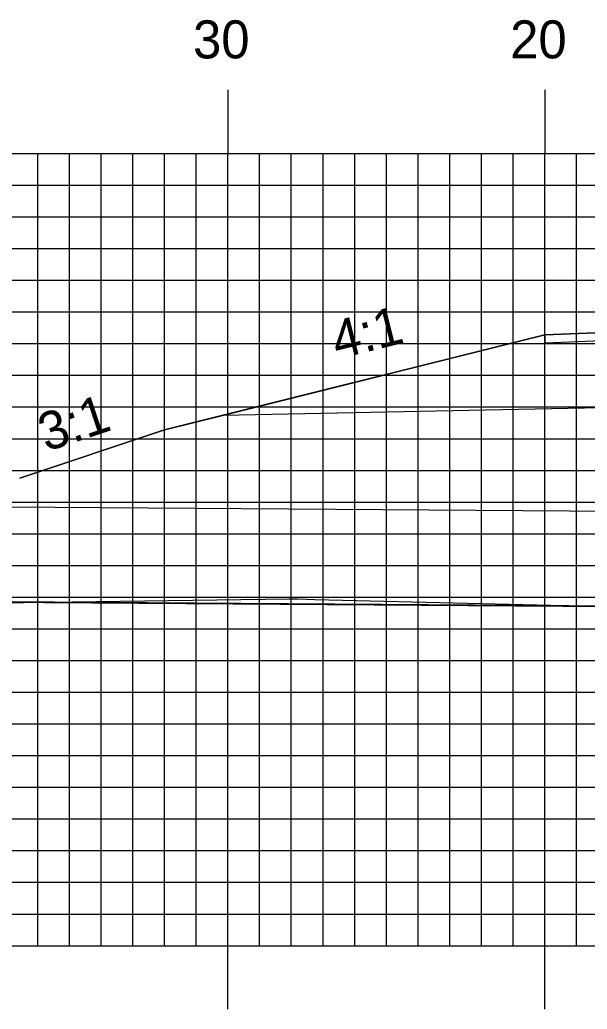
# Model space of a CAD drawing. Extents: x 1819244 to 1819587, y 442591 to 442811.
# Drawn here: x 1819373.09 to 1819391.01, y 442741.66 to 442772.88 of the extents above; entities that cross this region are included whole.
import ezdxf

# ---------------------------------------------------------------- set-up
doc = ezdxf.new("R2010")
doc.units = 0
for name, color, linetype in [('ANNOTATION', 7, 'Continuous'), ('D_Drainage_Culvert', 7, 'Continuous'), ('D_Roadway_Centerline', 7, 'Continuous'), ('D_Roadway_Edge_Shoulder', 7, 'Continuous'), ('D_Roadway_SlopeLines', 7, 'Continuous'), ('D_Roadway_SubGrade', 7, 'Continuous'), ('H_V ANNOTATION', 7, 'Continuous'), ('MAJOR', 7, 'Continuous'), ('MINOR', 7, 'Continuous'), ('S_Roadway_Centerline', 7, 'Continuous')]:
    doc.layers.add(name, color=color, linetype=linetype)

msp = doc.modelspace()

# ---------------------------------------------------------------- linework, layer by layer
at = {"layer": 'D_Drainage_Culvert'}
msp.add_line((1819364.881, 442754.558), (1819456.879, 442753.917), dxfattribs=at)
msp.add_lwpolyline([(1819360.881, 442754.596), (1819360.902, 442757.596), (1819456.9, 442756.917), (1819456.879, 442753.917)], close=True, dxfattribs=at)
at = {"layer": 'D_Roadway_Centerline'}
msp.add_lwpolyline([(1819373.094, 442758.418), (1819377.665, 442759.942), (1819379.491, 442760.398), (1819389.665, 442762.942), (1819397.665, 442763.262), (1819409.665, 442763.502), (1819421.665, 442763.262), (1819429.665, 442762.942), (1819439.839, 442760.398), (1819441.665, 442759.942), (1819448.263, 442757.86)], dxfattribs=at)
at = {"layer": 'D_Roadway_Edge_Shoulder'}
msp.add_lwpolyline([(1819397.665, 442763.262), (1819389.665, 442762.942), (1819389.665, 442762.692), (1819397.665, 442763.012)], close=True, dxfattribs=at)
at = {"layer": 'D_Roadway_SlopeLines'}
msp.add_lwpolyline([(1819389.665, 442762.942), (1819377.665, 442759.942), (1819373.094, 442758.418)], dxfattribs=at)
at = {"layer": 'D_Roadway_SubGrade'}
msp.add_lwpolyline([(1819397.665, 442760.762), (1819379.491, 442760.398), (1819389.665, 442762.942), (1819389.665, 442762.692), (1819397.665, 442763.012), (1819409.665, 442763.252), (1819421.665, 442763.012), (1819429.665, 442762.692), (1819429.665, 442762.942), (1819439.839, 442760.398), (1819421.665, 442760.762), (1819409.665, 442761.002)], close=True, dxfattribs=at)
at = {"layer": 'MAJOR'}
for p, q in [((1819379.665, 442770.669), (1819379.665, 442768.665)), ((1819389.665, 442770.669), (1819389.665, 442768.665)), ((1819269.665, 442768.665), (1819549.665, 442768.665)), ((1819269.665, 442768.665), (1819549.665, 442768.665)), ((1819379.665, 442743.665), (1819379.665, 442768.665)), ((1819389.665, 442743.665), (1819389.665, 442768.665)), ((1819269.665, 442763.665), (1819549.665, 442763.665)), ((1819269.665, 442758.665), (1819549.665, 442758.665)), ((1819269.665, 442753.665), (1819549.665, 442753.665)), ((1819269.665, 442748.665), (1819549.665, 442748.665)), ((1819269.665, 442743.665), (1819549.665, 442743.665)), ((1819269.665, 442743.665), (1819549.665, 442743.665)), ((1819379.665, 442741.661), (1819379.665, 442743.665)), ((1819389.665, 442741.661), (1819389.665, 442743.665))]:
    msp.add_line(p, q, dxfattribs=at)
at = {"layer": 'MINOR'}
for p, q in [((1819373.665, 442743.665), (1819373.665, 442768.665)), ((1819374.665, 442743.665), (1819374.665, 442768.665)), ((1819375.665, 442743.665), (1819375.665, 442768.665)), ((1819376.665, 442743.665), (1819376.665, 442768.665)), ((1819377.665, 442743.665), (1819377.665, 442768.665)), ((1819378.665, 442743.665), (1819378.665, 442768.665)), ((1819380.665, 442743.665), (1819380.665, 442768.665)), ((1819381.665, 442743.665), (1819381.665, 442768.665)), ((1819382.665, 442743.665), (1819382.665, 442768.665)), ((1819383.665, 442743.665), (1819383.665, 442768.665)), ((1819384.665, 442743.665), (1819384.665, 442768.665)), ((1819385.665, 442743.665), (1819385.665, 442768.665)), ((1819386.665, 442743.665), (1819386.665, 442768.665)), ((1819387.665, 442743.665), (1819387.665, 442768.665)), ((1819388.665, 442743.665), (1819388.665, 442768.665)), ((1819390.665, 442743.665), (1819390.665, 442768.665)), ((1819269.665, 442767.665), (1819549.665, 442767.665)), ((1819269.665, 442766.665), (1819549.665, 442766.665)), ((1819269.665, 442765.665), (1819549.665, 442765.665)), ((1819269.665, 442764.665), (1819549.665, 442764.665)), ((1819269.665, 442762.665), (1819549.665, 442762.665)), ((1819269.665, 442761.665), (1819549.665, 442761.665)), ((1819269.665, 442760.665), (1819549.665, 442760.665)), ((1819269.665, 442759.665), (1819549.665, 442759.665)), ((1819269.665, 442757.665), (1819549.665, 442757.665)), ((1819269.665, 442756.665), (1819549.665, 442756.665)), ((1819269.665, 442755.665), (1819549.665, 442755.665)), ((1819269.665, 442754.665), (1819549.665, 442754.665)), ((1819269.665, 442752.665), (1819549.665, 442752.665)), ((1819269.665, 442751.665), (1819549.665, 442751.665)), ((1819269.665, 442750.665), (1819549.665, 442750.665)), ((1819269.665, 442749.665), (1819549.665, 442749.665)), ((1819269.665, 442747.665), (1819549.665, 442747.665)), ((1819269.665, 442746.665), (1819549.665, 442746.665)), ((1819269.665, 442745.665), (1819549.665, 442745.665)), ((1819269.665, 442744.665), (1819549.665, 442744.665))]:
    msp.add_line(p, q, dxfattribs=at)
at = {"layer": 'S_Roadway_Centerline'}
msp.add_lwpolyline([(1819269.665, 442757.95), (1819272.752, 442757.702), (1819292.958, 442756.18), (1819302.01, 442755.845), (1819313.002, 442755.778), (1819320.093, 442755.729), (1819329.655, 442755.679), (1819340.464, 442755.086), (1819358.276, 442754.65), (1819368.644, 442754.436), (1819381.597, 442754.609), (1819381.856, 442754.609), (1819382.406, 442754.589), (1819415.248, 442753.801), (1819428.01, 442753.581), (1819435.779, 442753.54), (1819448.768, 442753.643), (1819449.398, 442753.657), (1819462.466, 442753.958), (1819468.069, 442753.858), (1819486.973, 442753.903)], dxfattribs=at)

# ---------------------------------------------------------------- texts
at = {"layer": 'ANNOTATION'}
for s, rotation, p in [('4:1', 14.0362, (1819383.113, 442762.165)), ('3:1', 18.4348, (1819373.927, 442759.244))]:
    msp.add_text(s, height=1.2, rotation=rotation, dxfattribs=at).set_placement(p)
at = {"layer": 'H_V ANNOTATION'}
for s, p in [('30', (1819378.562, 442771.665)), ('20', (1819388.573, 442771.665))]:
    msp.add_text(s, height=1.2, dxfattribs=at).set_placement(p)

doc.saveas('drawing.dxf')
